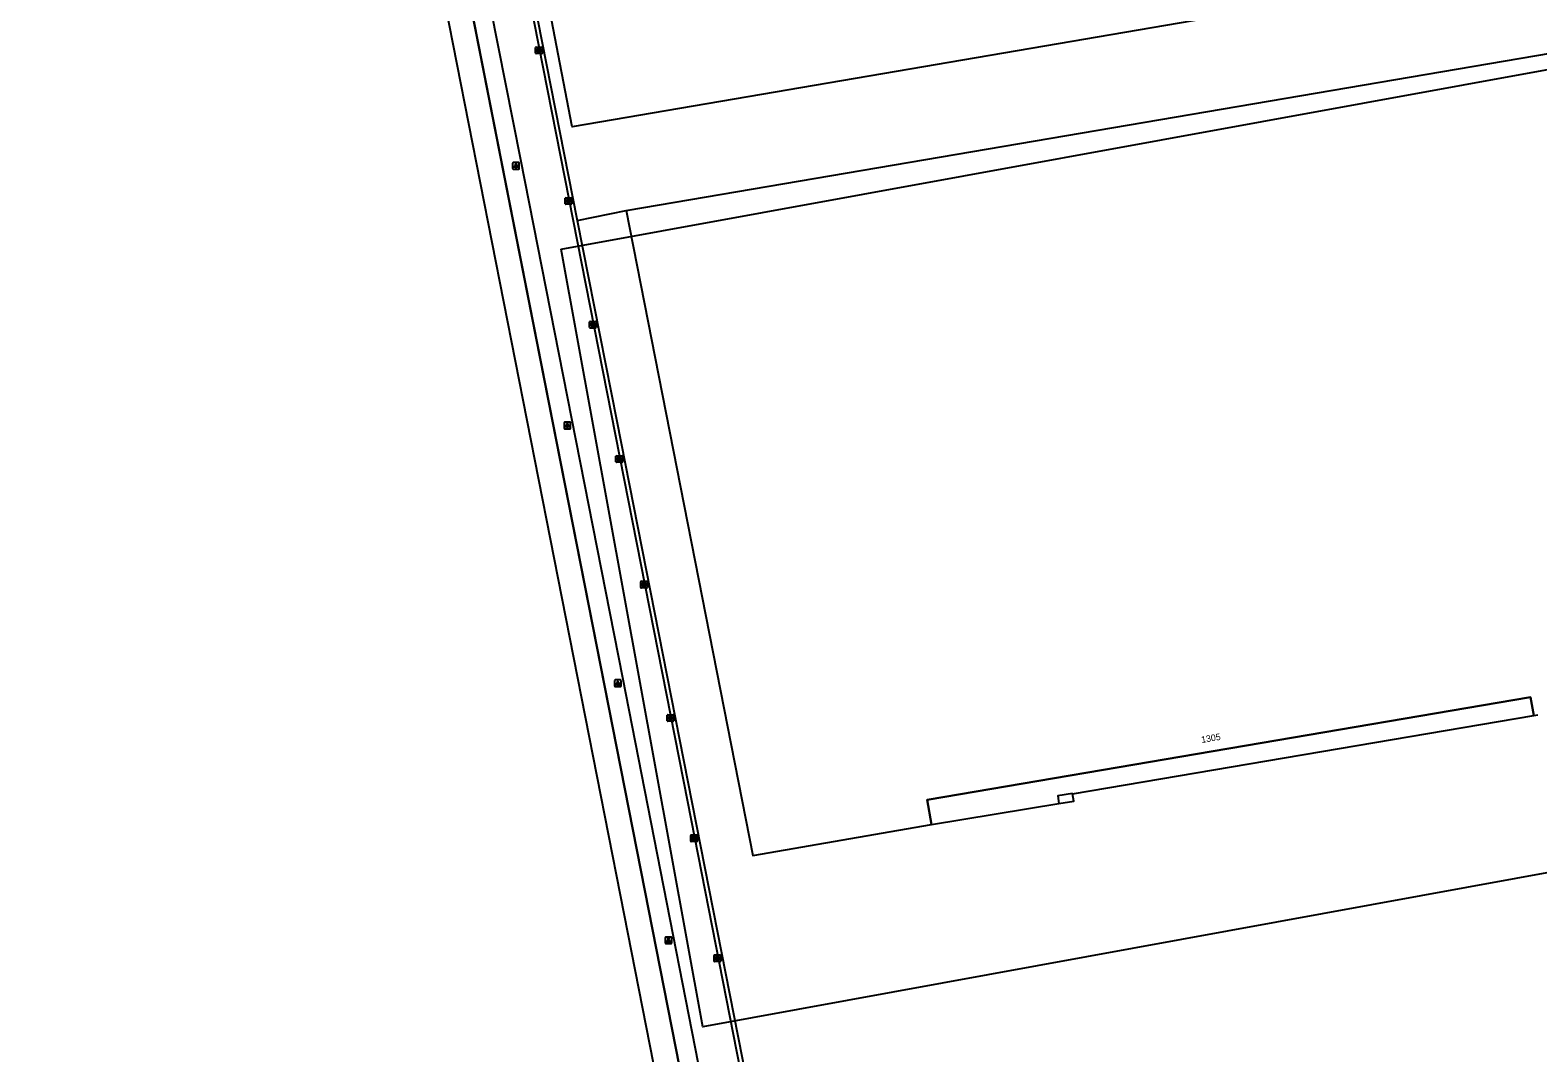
# Model space of a CAD drawing. Extents: x 154324 to 155743, y 382939 to 384183.
# Drawn here: x 154331.8 to 154562, y 383124 to 383280 of the extents above; entities that cross this region are included whole.
import ezdxf

# ---------------------------------------------------------------- set-up
doc = ezdxf.new("R2010")
doc.units = 0
for name, color, linetype in [('IMGEO_Bouwland', 7, 'Continuous'), ('IMGEO_Hek', 7, 'Continuous'), ('IMGEO_Kolk', 7, 'Continuous'), ('IMGEO_Lichtpunt', 7, 'Continuous'), ('IMGEO_Loofbos', 7, 'Continuous'), ('IMGEO_Pand', 7, 'Continuous'), ('IMGEO_Pand_nummerreeks', 7, 'Continuous'), ('IMGEO_Pand_overbouw', 7, 'Continuous'), ('IMGEO_Pand_vergunning_verleend', 7, 'Continuous'), ('IMGEO_Rijbaan_lokaal_gesloten', 7, 'Continuous')]:
    doc.layers.add(name, color=color, linetype=linetype)

msp = doc.modelspace()

# ---------------------------------------------------------------- linework, layer by layer
at = {"layer": 'IMGEO_Bouwland'}
for points in [[(154335.86, 383605.18), (154395.89, 383300.08), (154425.66, 383148.76), (154440.92, 383071.1)], [(154415.36, 383251.02), (154422.8, 383252.54)]]:
    msp.add_lwpolyline(points, dxfattribs=at)
at = {"layer": 'IMGEO_Hek'}
msp.add_lwpolyline([(154435.67, 383072.5), (154440.92, 383071.1), (154425.66, 383148.76), (154335.86, 383605.18)], dxfattribs=at)
at = {"layer": 'IMGEO_Kolk'}
for p, q in [((154408.99, 383276.54), (154408.99, 383277.39)), ((154409.07, 383277.47), (154409.92, 383277.47)), ((154409.92, 383276.47), (154409.07, 383276.47)), ((154409.48, 383277.25), (154409.51, 383277.25)), ((154409.5, 383276.69), (154409.48, 383276.69)), ((154409.99, 383277.39), (154409.99, 383276.54)), ((154413.51, 383253.56), (154413.51, 383254.41)), ((154413.59, 383254.48), (154414.44, 383254.48)), ((154414.44, 383253.48), (154413.59, 383253.48)), ((154414, 383254.26), (154414.02, 383254.26)), ((154414.02, 383253.7), (154414, 383253.7)), ((154414.51, 383254.41), (154414.51, 383253.56)), ((154417.24, 383234.66), (154417.24, 383235.52)), ((154417.31, 383235.59), (154418.16, 383235.59)), ((154418.16, 383234.59), (154417.31, 383234.59)), ((154417.72, 383235.37), (154417.75, 383235.37)), ((154417.75, 383234.81), (154417.72, 383234.81)), ((154418.24, 383235.52), (154418.24, 383234.66)), ((154421.26, 383214.18), (154421.26, 383215.03)), ((154421.34, 383215.1), (154422.19, 383215.1)), ((154422.19, 383214.1), (154421.34, 383214.1)), ((154421.75, 383214.88), (154421.77, 383214.88)), ((154421.77, 383214.32), (154421.75, 383214.32)), ((154422.26, 383215.03), (154422.26, 383214.18)), ((154425.06, 383195.01), (154425.06, 383195.86)), ((154425.13, 383195.94), (154425.99, 383195.94)), ((154425.99, 383194.94), (154425.13, 383194.94)), ((154425.55, 383195.72), (154425.57, 383195.72)), ((154425.57, 383195.16), (154425.55, 383195.16)), ((154426.06, 383195.86), (154426.06, 383195.01)), ((154429.09, 383174.64), (154429.09, 383175.5)), ((154429.16, 383175.57), (154430.02, 383175.57)), ((154430.02, 383174.57), (154429.16, 383174.57)), ((154429.6, 383174.79), (154429.57, 383174.79)), ((154429.58, 383175.35), (154429.6, 383175.35)), ((154430.09, 383175.5), (154430.09, 383174.64)), ((154432.68, 383156.29), (154432.68, 383157.15)), ((154432.75, 383157.22), (154433.6, 383157.22)), ((154433.6, 383156.22), (154432.75, 383156.22)), ((154433.16, 383157), (154433.19, 383157)), ((154433.19, 383156.44), (154433.16, 383156.44)), ((154433.68, 383157.15), (154433.68, 383156.29)), ((154436.26, 383137.98), (154436.26, 383138.83)), ((154436.33, 383138.91), (154437.18, 383138.91)), ((154437.18, 383137.91), (154436.33, 383137.91)), ((154436.74, 383138.69), (154436.77, 383138.69)), ((154436.77, 383138.13), (154436.74, 383138.13)), ((154437.26, 383138.83), (154437.26, 383137.98))]:
    msp.add_line(p, q, dxfattribs=at)
for points in [[(154408.99, 383276.54), (154408.99, 383277.39)], [(154409.07, 383277.47), (154409.92, 383277.47)], [(154409.92, 383276.47), (154409.07, 383276.47)], [(154409.31, 383277.17), (154409.44, 383277.17), (154409.44, 383277.01), (154409.57, 383277.17), (154409.73, 383277.17), (154409.58, 383277.02), (154409.74, 383276.77), (154409.58, 383276.77), (154409.5, 383276.93), (154409.44, 383276.86), (154409.44, 383276.77), (154409.31, 383276.77), (154409.31, 383277.17)], [(154409.99, 383277.39), (154409.99, 383276.54)], [(154413.51, 383253.56), (154413.51, 383254.41)], [(154413.59, 383254.48), (154414.44, 383254.48)], [(154414.44, 383253.48), (154413.59, 383253.48)], [(154413.83, 383254.18), (154413.96, 383254.18), (154413.96, 383254.03), (154414.08, 383254.18), (154414.25, 383254.18), (154414.1, 383254.03), (154414.26, 383253.78), (154414.1, 383253.78), (154414.02, 383253.95), (154413.96, 383253.88), (154413.96, 383253.78), (154413.83, 383253.78), (154413.83, 383254.18)], [(154414.51, 383254.41), (154414.51, 383253.56)], [(154417.24, 383234.66), (154417.24, 383235.52)], [(154417.31, 383235.59), (154418.16, 383235.59)], [(154418.16, 383234.59), (154417.31, 383234.59)], [(154417.56, 383235.29), (154417.68, 383235.29), (154417.68, 383235.14), (154417.81, 383235.29), (154417.97, 383235.29), (154417.83, 383235.14), (154417.98, 383234.89), (154417.83, 383234.89), (154417.74, 383235.06), (154417.68, 383234.99), (154417.68, 383234.89), (154417.56, 383234.89), (154417.56, 383235.29)], [(154418.24, 383235.52), (154418.24, 383234.66)], [(154421.26, 383214.18), (154421.26, 383215.03)], [(154421.34, 383215.1), (154422.19, 383215.1)], [(154422.19, 383214.1), (154421.34, 383214.1)], [(154421.58, 383214.8), (154421.71, 383214.8), (154421.71, 383214.65), (154421.83, 383214.8), (154422, 383214.8), (154421.85, 383214.65), (154422.01, 383214.4), (154421.85, 383214.4), (154421.77, 383214.57), (154421.71, 383214.5), (154421.71, 383214.4), (154421.58, 383214.4), (154421.58, 383214.8)], [(154422.26, 383215.03), (154422.26, 383214.18)], [(154425.06, 383195.01), (154425.06, 383195.86)], [(154425.13, 383195.94), (154425.99, 383195.94)], [(154425.99, 383194.94), (154425.13, 383194.94)], [(154425.38, 383195.64), (154425.5, 383195.64), (154425.5, 383195.48), (154425.63, 383195.64), (154425.8, 383195.64), (154425.65, 383195.49), (154425.8, 383195.24), (154425.65, 383195.24), (154425.57, 383195.4), (154425.5, 383195.33), (154425.5, 383195.24), (154425.38, 383195.24), (154425.38, 383195.64)], [(154426.06, 383195.86), (154426.06, 383195.01)], [(154429.09, 383174.64), (154429.09, 383175.5)], [(154429.16, 383175.57), (154430.02, 383175.57)], [(154430.02, 383174.57), (154429.16, 383174.57)], [(154429.41, 383175.27), (154429.53, 383175.27), (154429.53, 383175.12), (154429.66, 383175.27), (154429.83, 383175.27), (154429.68, 383175.12), (154429.83, 383174.87), (154429.68, 383174.87), (154429.6, 383175.03), (154429.53, 383174.97), (154429.53, 383174.87), (154429.41, 383174.87), (154429.41, 383175.27)], [(154430.09, 383175.5), (154430.09, 383174.64)], [(154432.68, 383156.29), (154432.68, 383157.15)], [(154432.75, 383157.22), (154433.6, 383157.22)], [(154433.6, 383156.22), (154432.75, 383156.22)], [(154433, 383156.92), (154433.12, 383156.92), (154433.12, 383156.77), (154433.25, 383156.92), (154433.41, 383156.92), (154433.27, 383156.77), (154433.42, 383156.52), (154433.27, 383156.52), (154433.18, 383156.68), (154433.12, 383156.62), (154433.12, 383156.52), (154433, 383156.52), (154433, 383156.92)], [(154433.68, 383157.15), (154433.68, 383156.29)], [(154436.26, 383137.98), (154436.26, 383138.83)], [(154436.33, 383138.91), (154437.18, 383138.91)], [(154437.18, 383137.91), (154436.33, 383137.91)], [(154436.58, 383138.61), (154436.7, 383138.61), (154436.7, 383138.46), (154436.83, 383138.61), (154436.99, 383138.61), (154436.85, 383138.46), (154437, 383138.21), (154436.85, 383138.21), (154436.76, 383138.37), (154436.7, 383138.3), (154436.7, 383138.21), (154436.58, 383138.21), (154436.58, 383138.61)], [(154437.26, 383138.83), (154437.26, 383137.98)]]:
    msp.add_lwpolyline(points, dxfattribs=at)
for centre, start, end in [((154409.07, 383277.39), 91.552, 178.448), ((154409.07, 383277.39), 91.552, 178.448), ((154409.07, 383276.54), 181.552, 268.448), ((154409.07, 383276.54), 181.552, 268.448), ((154409.92, 383277.39), 1.552, 88.448), ((154409.92, 383277.39), 1.552, 88.448), ((154409.92, 383276.54), 271.552, 358.448), ((154409.92, 383276.54), 271.552, 358.448), ((154413.59, 383254.41), 91.552, 178.448), ((154413.59, 383254.41), 91.552, 178.448), ((154413.59, 383253.56), 181.552, 268.448), ((154413.59, 383253.56), 181.552, 268.448), ((154414.44, 383254.41), 1.552, 88.448), ((154414.44, 383254.41), 1.552, 88.448), ((154414.44, 383253.56), 271.552, 358.448), ((154414.44, 383253.56), 271.552, 358.448), ((154417.31, 383235.52), 91.552, 178.448), ((154417.31, 383235.52), 91.552, 178.448), ((154417.31, 383234.67), 181.552, 268.448), ((154417.31, 383234.67), 181.552, 268.448), ((154418.16, 383235.52), 1.552, 88.448), ((154418.16, 383235.52), 1.552, 88.448), ((154418.16, 383234.67), 271.552, 358.448), ((154418.16, 383234.67), 271.552, 358.448), ((154421.34, 383215.03), 91.552, 178.448), ((154421.34, 383215.03), 91.552, 178.448), ((154421.34, 383214.18), 181.552, 268.448), ((154421.34, 383214.18), 181.552, 268.448), ((154422.19, 383215.03), 1.552, 88.448), ((154422.19, 383215.03), 1.552, 88.448), ((154422.19, 383214.18), 271.552, 358.448), ((154422.19, 383214.18), 271.552, 358.448), ((154425.14, 383195.86), 91.552, 178.448), ((154425.14, 383195.86), 91.552, 178.448), ((154425.14, 383195.01), 181.552, 268.448), ((154425.14, 383195.01), 181.552, 268.448), ((154425.98, 383195.86), 1.552, 88.448), ((154425.98, 383195.86), 1.552, 88.448), ((154425.98, 383195.01), 271.552, 358.448), ((154425.98, 383195.01), 271.552, 358.448), ((154429.17, 383175.49), 91.552, 178.448), ((154429.17, 383175.49), 91.552, 178.448), ((154429.17, 383174.64), 181.552, 268.448), ((154429.17, 383174.64), 181.552, 268.448), ((154430.01, 383175.49), 1.552, 88.448), ((154430.01, 383175.49), 1.552, 88.448), ((154430.01, 383174.64), 271.552, 358.448), ((154430.01, 383174.64), 271.552, 358.448), ((154432.75, 383157.14), 91.552, 178.448), ((154432.75, 383157.14), 91.552, 178.448), ((154432.75, 383156.29), 181.552, 268.448), ((154432.75, 383156.29), 181.552, 268.448), ((154433.6, 383157.14), 1.552, 88.448), ((154433.6, 383157.14), 1.552, 88.448), ((154433.6, 383156.29), 271.552, 358.448), ((154433.6, 383156.29), 271.552, 358.448), ((154436.33, 383138.83), 91.552, 178.448), ((154436.33, 383138.83), 91.552, 178.448), ((154436.33, 383137.98), 181.552, 268.448), ((154436.33, 383137.98), 181.552, 268.448), ((154437.18, 383138.83), 1.552, 88.448), ((154437.18, 383138.83), 1.552, 88.448), ((154437.18, 383137.98), 271.552, 358.448), ((154437.18, 383137.98), 271.552, 358.448)]:
    msp.add_arc(centre, 0.0765, start, end, dxfattribs=at)
for centre, major_axis, ratio, start_param, end_param in [((154409.48, 383276.97), (-0.387, 0.002), 0.722429, 4.712389, 7.853982), ((154409.5, 383276.97), (-0.39, 0.002), 0.717154, 1.570796, 4.712389), ((154414, 383253.98), (-0.387, 0.002), 0.722429, 4.712389, 7.853982), ((154414.02, 383253.98), (-0.39, 0.002), 0.717154, 1.570796, 4.712389), ((154417.72, 383235.09), (-0.387, 0.002), 0.722429, 4.712389, 7.853982), ((154417.75, 383235.09), (-0.39, 0.002), 0.717154, 1.570796, 4.712389), ((154421.75, 383214.6), (-0.387, 0.002), 0.722429, 4.712389, 7.853982), ((154421.77, 383214.6), (-0.39, 0.002), 0.717154, 1.570796, 4.712389), ((154425.55, 383195.44), (-0.387, 0.002), 0.722429, 4.712389, 7.853982), ((154425.57, 383195.44), (-0.39, 0.002), 0.717154, 1.570796, 4.712389), ((154429.58, 383175.07), (-0.387, 0.002), 0.722429, 4.712389, 7.853982), ((154429.6, 383175.07), (-0.39, 0.002), 0.717154, 1.570796, 4.712389), ((154433.16, 383156.72), (-0.387, 0.002), 0.722429, 4.712389, 7.853982), ((154433.19, 383156.72), (-0.39, 0.002), 0.717154, 1.570796, 4.712389), ((154436.74, 383138.41), (-0.387, 0.002), 0.722429, 4.712389, 7.853982), ((154436.77, 383138.41), (-0.39, 0.002), 0.717154, 1.570796, 4.712389)]:
    msp.add_ellipse(centre, major_axis=major_axis, ratio=ratio, start_param=start_param, end_param=end_param, dxfattribs=at)
at = {"layer": 'IMGEO_Lichtpunt'}
for p, q in [((154405.49, 383259.74), (154405.49, 383258.94)), ((154405.49, 383259.74), (154405.49, 383258.94)), ((154406.4, 383259.84), (154405.59, 383259.84)), ((154406.4, 383259.84), (154405.59, 383259.84)), ((154406.49, 383258.94), (154406.49, 383259.74)), ((154406.49, 383258.94), (154406.49, 383259.74)), ((154405.59, 383258.84), (154406.4, 383258.84)), ((154405.59, 383258.84), (154406.4, 383258.84)), ((154414.23, 383220.21), (154413.42, 383220.21)), ((154414.23, 383220.21), (154413.42, 383220.21)), ((154413.33, 383220.12), (154413.33, 383219.31)), ((154413.33, 383220.12), (154413.33, 383219.31)), ((154413.42, 383219.21), (154414.23, 383219.21)), ((154413.42, 383219.21), (154414.23, 383219.21)), ((154414.32, 383219.31), (154414.32, 383220.12)), ((154414.32, 383219.31), (154414.32, 383220.12)), ((154421.05, 383180.77), (154421.05, 383179.96)), ((154421.05, 383180.77), (154421.05, 383179.96)), ((154421.95, 383180.87), (154421.15, 383180.87)), ((154421.95, 383180.87), (154421.15, 383180.87)), ((154421.15, 383179.87), (154421.95, 383179.87)), ((154421.15, 383179.87), (154421.95, 383179.87)), ((154422.05, 383179.96), (154422.05, 383180.77)), ((154422.05, 383179.96), (154422.05, 383180.77)), ((154428.79, 383141.53), (154428.79, 383140.72)), ((154428.79, 383141.53), (154428.79, 383140.72)), ((154429.69, 383141.62), (154428.88, 383141.62)), ((154429.69, 383141.62), (154428.88, 383141.62)), ((154428.88, 383140.63), (154429.69, 383140.63)), ((154428.88, 383140.63), (154429.69, 383140.63)), ((154429.79, 383140.72), (154429.79, 383141.53)), ((154429.79, 383140.72), (154429.79, 383141.53))]:
    msp.add_line(p, q, dxfattribs=at)
for points in [[(154405.87, 383259.41), (154405.91, 383259.38), (154405.72, 383259.12), (154405.68, 383259.14), (154405.87, 383259.41)], [(154405.97, 383259.36), (154406.02, 383259.36), (154406.02, 383259.04), (154405.97, 383259.04), (154405.97, 383259.36)], [(154406.08, 383259.38), (154406.12, 383259.41), (154406.3, 383259.14), (154406.27, 383259.12), (154406.08, 383259.38)], [(154413.7, 383219.78), (154413.74, 383219.75), (154413.55, 383219.49), (154413.51, 383219.52), (154413.7, 383219.78)], [(154413.8, 383219.73), (154413.85, 383219.73), (154413.85, 383219.41), (154413.8, 383219.41), (154413.8, 383219.73)], [(154413.91, 383219.75), (154413.95, 383219.78), (154414.14, 383219.52), (154414.1, 383219.49), (154413.91, 383219.75)], [(154421.43, 383180.43), (154421.46, 383180.41), (154421.28, 383180.14), (154421.24, 383180.17), (154421.43, 383180.43)], [(154421.53, 383180.39), (154421.58, 383180.39), (154421.58, 383180.06), (154421.53, 383180.06), (154421.53, 383180.39)], [(154421.64, 383180.41), (154421.68, 383180.43), (154421.86, 383180.17), (154421.82, 383180.14), (154421.64, 383180.41)], [(154429.16, 383141.19), (154429.2, 383141.16), (154429.02, 383140.9), (154428.98, 383140.93), (154429.16, 383141.19)], [(154429.27, 383141.14), (154429.31, 383141.14), (154429.31, 383140.82), (154429.27, 383140.82), (154429.27, 383141.14)], [(154429.38, 383141.16), (154429.41, 383141.19), (154429.6, 383140.93), (154429.56, 383140.9), (154429.38, 383141.16)]]:
    msp.add_lwpolyline(points, dxfattribs=at)
for centre in [(154405.99, 383259.54), (154413.83, 383219.91), (154421.55, 383180.57), (154429.29, 383141.33)]:
    msp.add_circle(centre, 0.0994, dxfattribs=at)
for centre, start, end in [((154405.59, 383259.74), 90, 180), ((154405.59, 383259.74), 90, 180), ((154406.4, 383259.74), 0, 90), ((154406.4, 383259.74), 0, 90), ((154405.59, 383258.94), 180, 270), ((154405.59, 383258.94), 180, 270), ((154406.4, 383258.94), 270, 0), ((154406.4, 383258.94), 270, 360), ((154413.42, 383220.12), 90, 180), ((154413.42, 383220.12), 90, 180), ((154414.23, 383220.12), 0, 90), ((154414.23, 383220.12), 0, 90), ((154413.42, 383219.31), 180, 270), ((154413.42, 383219.31), 180, 270), ((154414.23, 383219.31), 270, 0), ((154414.23, 383219.31), 270, 360), ((154421.15, 383180.77), 90, 180), ((154421.15, 383180.77), 90, 180), ((154421.15, 383179.96), 180, 270), ((154421.15, 383179.96), 180, 270), ((154421.95, 383180.77), 0, 90), ((154421.95, 383180.77), 0, 90), ((154421.95, 383179.96), 270, 0), ((154421.95, 383179.96), 270, 360), ((154428.88, 383141.53), 90, 180), ((154428.88, 383141.53), 90, 180), ((154428.88, 383140.72), 180, 270), ((154428.88, 383140.72), 180, 270), ((154429.69, 383141.53), 0, 90), ((154429.69, 383141.53), 0, 90), ((154429.69, 383140.72), 270, 0), ((154429.69, 383140.72), 270, 360)]:
    msp.add_arc(centre, 0.0946, start, end, dxfattribs=at)
at = {"layer": 'IMGEO_Loofbos'}
msp.add_lwpolyline([(154434.86, 383076.6), (154436.08, 383076.28), (154421.98, 383148.04), (154332.89, 383600.85), (154331.81, 383600.36)], dxfattribs=at)
at = {"layer": 'IMGEO_Pand'}
for points in [[(154422.8, 383252.54), (154564.29, 383276.58)], [(154422.8, 383252.54), (154442.14, 383154.08), (154469.46, 383158.8), (154468.8, 383162.6), (154560.93, 383178.26), (154561.39, 383175.43), (154562.03, 383175.54)], [(154490.98, 383163.56), (154488.72, 383163.17), (154488.9, 383162.01), (154491.18, 383162.38), (154490.99, 383163.49), (154490.98, 383163.56)]]:
    msp.add_lwpolyline(points, dxfattribs=at)
at = {"layer": 'IMGEO_Pand_overbouw'}
msp.add_lwpolyline([(154469.46, 383158.8), (154488.9, 383162.01), (154491.18, 383162.38), (154490.99, 383163.49), (154561.39, 383175.43), (154560.93, 383178.26), (154468.8, 383162.6)], close=True, dxfattribs=at)
at = {"layer": 'IMGEO_Pand_vergunning_verleend'}
for points in [[(154548.37, 383288.17), (154414.6, 383265.31), (154403.03, 383325.33)], [(154412.9, 383246.6), (154566.07, 383274.51), (154587.69, 383155.85), (154434.52, 383127.94), (154412.9, 383246.6)]]:
    msp.add_lwpolyline(points, dxfattribs=at)
at = {"layer": 'IMGEO_Rijbaan_lokaal_gesloten'}
for points in [[(154461.51, 382981.55), (154450.87, 383035.65), (154439.15, 383095.25), (154422.31, 383181.22), (154406.72, 383260.28), (154396.48, 383312.17), (154394.42, 383322.32), (154392.95, 383329.96)], [(154466.46, 382988.22), (154463.94, 383001.02), (154453.69, 383053.15), (154432.24, 383162.26), (154411.51, 383267.43), (154400.66, 383322.48)], [(154401.25, 383322.6), (154415.36, 383251.02)], [(154415.36, 383251.02), (154421.4, 383220.37), (154444.99, 383100.45), (154464.56, 383001.13), (154467.07, 382988.36)]]:
    msp.add_lwpolyline(points, dxfattribs=at)

# ---------------------------------------------------------------- texts
at = {"layer": 'IMGEO_Pand_nummerreeks'}
msp.add_text('1305', height=1, rotation=9.6429, dxfattribs=at).set_placement((154510.72, 383171.25))

doc.saveas('drawing.dxf')
